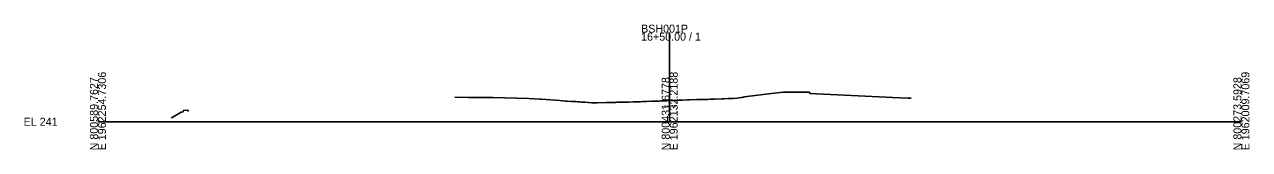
# Model space of a CAD drawing. Extents: x -26 to 1403, y -10 to 19587.
# Drawn here: x -25.7 to 402.8, y 490.3 to 534 of the extents above; entities that cross this region are included whole.
import ezdxf

# ---------------------------------------------------------------- set-up
doc = ezdxf.new("R2010")
doc.units = 0
for name, color, linetype in [('Default', 7, 'Continuous'), ('RD_GPK_XS_Cell', 7, 'Continuous'), ('RD_XS_ExGround', 7, 'Continuous'), ('RD_XS_TX_Elev_EX', 7, 'Continuous')]:
    doc.layers.add(name, color=color, linetype=linetype)

msp = doc.modelspace()

# ---------------------------------------------------------------- linework, layer by layer
at = {"layer": 'RD_GPK_XS_Cell'}
for p, q in [((200, 500), (200, 531.16)), ((0, 500), (200, 500)), ((200, 500), (400, 500))]:
    msp.add_line(p, q, dxfattribs=at)
at = {"layer": 'RD_XS_ExGround'}
for points in [[(124.83, 508.55), (129.6, 508.47), (131.61, 508.52), (138.13, 508.54), (150.68, 508.14), (154.63, 507.92), (155.12, 507.89), (161.54, 507.41), (162.57, 507.34), (163.59, 507.25), (164.18, 507.21), (165.45, 507.13), (166.46, 507.08), (167.15, 507.05), (167.79, 507.02), (168.57, 506.95), (169.13, 506.91), (170.05, 506.86), (170.29, 506.87), (171.52, 506.77), (172.79, 506.66), (174.66, 506.67), (177.83, 506.72), (179.64, 506.75), (180.31, 506.77), (181, 506.79), (181.52, 506.8), (183.01, 506.84), (184.13, 506.86), (185.64, 506.9), (187.29, 506.94), (188.32, 506.96), (189.7, 507.01), (190.44, 507.03), (191.89, 507.09), (193.81, 507.17), (196.24, 507.26), (196.96, 507.29), (197.91, 507.32), (199.05, 507.35), (200, 507.38), (200.85, 507.41), (201.97, 507.46), (202.6, 507.48), (203.1, 507.5), (204.42, 507.54), (206.25, 507.62), (206.95, 507.64), (209.45, 507.73), (210.13, 507.75), (212.63, 507.82), (213.3, 507.84), (214.21, 507.86), (215.74, 507.91), (218.25, 508), (218.9, 508.02), (220.4, 508.1), (222.23, 508.18), (223.61, 508.27), (224.98, 508.47), (225.4, 508.54), (225.83, 508.62), (226.1, 508.68), (235.59, 509.85), (239.72, 510.39), (248.85, 510.36), (249.19, 509.84), (251.31, 509.76), (275.78, 508.62), (278, 508.51), (283.29, 508.28), (284.44, 508.23)], [(25.59, 501.32), (26.01, 501.49), (29.15, 503.34), (29.8, 503.44), (29.9, 503.96), (31.26, 504.03), (31.82, 503.75)]]:
    msp.add_lwpolyline(points, dxfattribs=at)

# ---------------------------------------------------------------- texts
at = {"layer": 'Default'}
msp.add_text('-', height=0.0001, dxfattribs=at).set_placement((0, 500))
at = {"layer": 'RD_GPK_XS_Cell'}
for s, p in [('BSH001P', (190, 531.16)), ('16+50.00 / 1', (190, 528.36)), ('EL 241', (-26, 498.6))]:
    msp.add_text(s, height=2.8, dxfattribs=at).set_placement(p)
for s, p in [('N 800589.7627', (0, 490)), ('E 1962254.7306', (2.8, 490)), ('N 800431.6778', (200, 490)), ('E 1962132.2188', (202.8, 490)), ('N 800273.5928', (400, 490)), ('E 1962009.7069', (402.8, 490))]:
    msp.add_text(s, height=2.8, rotation=90, dxfattribs=at).set_placement(p)
at = {"layer": 'RD_XS_TX_Elev_EX'}
msp.add_text('248.38', height=1, dxfattribs=at).set_placement((197.95, 504.88))

doc.saveas('drawing.dxf')
